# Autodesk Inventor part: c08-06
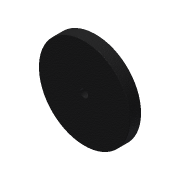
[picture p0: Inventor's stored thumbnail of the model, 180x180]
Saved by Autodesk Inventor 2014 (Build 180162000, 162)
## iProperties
Created: 2010-12
Part Number: c08-06
Document SubType Name: Modeling
Designer: Thom Tremblay
Density: 1 g/cm^3
Material: Generic
Appearance: Iron - Cast
Author: Thom Tremblay
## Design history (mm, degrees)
sketch "Sketch1"
  geometry: C1 r 6.413 at (0, 0); C2 r 74.93 at (0, 0); 1 further point
  constraints: 2 centre point, 2 coincident
  dimensions: "d0" = 12.827 diameter of C1; "d1" = 149.86 diameter of C2
extrude "Extrusion1" new body sketch "Sketch1" distance "d2" = 19.05; taper "d3" = 0 deg
chamfer "Chamfer1" distance "d4" = 0.762; stored, may be unused: second distance "d5" = 3.175, angle "d6" = 45 deg
body "Solid1"
